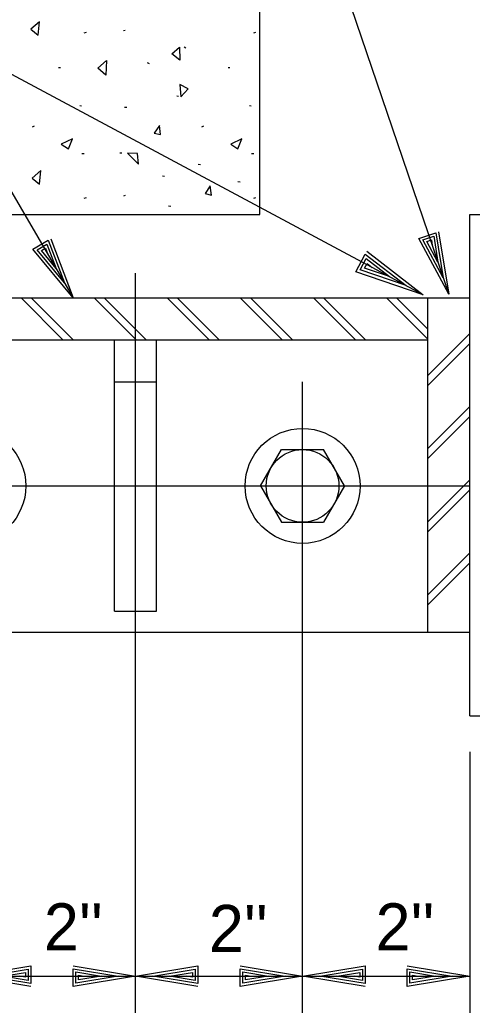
# Model space of a CAD drawing. Extents: x 22369.6 to 22389.4, y 22369.6 to 22386.
# Drawn here: x 22372.355 to 22372.806, y 22372.947 to 22373.93 of the extents above; entities that cross this region are included whole.
import ezdxf

# ---------------------------------------------------------------- set-up
doc = ezdxf.new("R2010")
doc.units = 0
for name, color, linetype in [('Level 1', 7, 'Continuous'), ('Level 10', 7, 'Continuous'), ('Level 2', 7, 'Continuous'), ('Level 4', 7, 'Continuous'), ('Level 50', 7, 'Continuous'), ('Level 7', 7, 'Continuous')]:
    doc.layers.add(name, color=color, linetype=linetype)

msp = doc.modelspace()

# ---------------------------------------------------------------- linework, layer by layer
at = {"layer": 'Level 1'}
for p, q in [((22372.4704, 22372.92825), (22372.4704, 22373.67725)), ((22372.39808, 22373.61084), (22372.35621, 22373.65272)), ((22372.40814, 22373.61084), (22372.36627, 22373.65272)), ((22372.471, 22373.61084), (22372.42912, 22373.65272)), ((22372.48105, 22373.61084), (22372.43918, 22373.65272)), ((22372.5439, 22373.61084), (22372.50203, 22373.65272)), ((22372.55397, 22373.61084), (22372.51209, 22373.65272)), ((22372.61682, 22373.61084), (22372.57495, 22373.65272)), ((22372.62687, 22373.61084), (22372.585, 22373.65272)), ((22372.68973, 22373.61084), (22372.64785, 22373.65272)), ((22372.69978, 22373.61084), (22372.6579, 22373.65272)), ((22372.76165, 22373.61182), (22372.72076, 22373.65272)), ((22372.76207, 22373.62147), (22372.73082, 22373.65272)), ((22372.76186, 22373.57539), (22372.80374, 22373.61727)), ((22372.76186, 22373.56534), (22372.80374, 22373.60722)), ((22372.63707, 22372.92308), (22372.63707, 22373.56918)), ((22372.76186, 22373.50249), (22372.80374, 22373.54436)), ((22372.76186, 22373.49244), (22372.80374, 22373.53431)), ((22372.59518, 22373.4653), (22372.61618, 22373.50168)), ((22372.61618, 22373.50168), (22372.65797, 22373.50168)), ((22372.67897, 22373.4653), (22372.65797, 22373.50168)), ((22372.76186, 22373.42958), (22372.80374, 22373.47146)), ((22372.13707, 22373.46522), (22372.80374, 22373.46522)), ((22372.59518, 22373.4653), (22372.61618, 22373.42895)), ((22372.67897, 22373.4653), (22372.65797, 22373.42895)), ((22372.76186, 22373.41952), (22372.80374, 22373.46139)), ((22372.61618, 22373.42895), (22372.65797, 22373.42895)), ((22372.76186, 22373.35666), (22372.80374, 22373.39854)), ((22372.76186, 22373.34661), (22372.80374, 22373.38849)), ((22372.80374, 22373.2), (22372.80374, 22372.76258)), ((22372.30374, 22372.9763), (22372.4704, 22372.9763)), ((22372.4704, 22372.9763), (22372.63707, 22372.9763)), ((22372.63707, 22372.9763), (22372.80374, 22372.9763))]:
    msp.add_line(p, q, dxfattribs=at)
for centre, radius in [((22372.30374, 22373.46522), 0.05729), ((22372.63707, 22373.46522), 0.05729), ((22372.63707, 22373.46522), 0.03627)]:
    msp.add_circle(centre, radius, dxfattribs=at)
at = {"layer": 'Level 10'}
for p, q in [((22372.75741, 22373.6559), (22371.83286, 22374.15046)), ((22372.74023, 22373.66509), (22372.74023, 22373.66509)), ((22372.75741, 22373.6559), (22372.75741, 22373.6559))]:
    msp.add_line(p, q, dxfattribs=at)
msp.add_lwpolyline([(22372.70106, 22373.69923), (22372.75741, 22373.6559), (22372.6901, 22373.67873), (22372.69948, 22373.69626), (22372.74023, 22373.66509), (22372.69451, 22373.68062), (22372.70053, 22373.69186), (22372.72369, 22373.67395), (22372.69893, 22373.68251), (22372.7014, 22373.68713), (22372.7065, 22373.68314)], dxfattribs=at)
at = {"layer": 'Level 2'}
for p, q in [((22372.39962, 22373.6677), (22372.39962, 22373.6677)), ((22372.7774, 22373.67273), (22372.7774, 22373.67273)), ((22372.78299, 22373.65632), (22372.78299, 22373.65632)), ((22372.40835, 22373.65272), (22372.40835, 22373.65272)), ((22372.45307, 22372.9763), (22372.45307, 22372.9763)), ((22372.4704, 22372.9763), (22372.4704, 22372.9763)), ((22372.4704, 22372.9763), (22372.4704, 22372.9763)), ((22372.48774, 22372.9763), (22372.48774, 22372.9763)), ((22372.61974, 22372.9763), (22372.61974, 22372.9763)), ((22372.63707, 22372.9763), (22372.63707, 22372.9763)), ((22372.63707, 22372.9763), (22372.63707, 22372.9763)), ((22372.6544, 22372.9763), (22372.6544, 22372.9763)), ((22372.7864, 22372.9763), (22372.7864, 22372.9763)), ((22372.80374, 22372.9763), (22372.80374, 22372.9763))]:
    msp.add_line(p, q, dxfattribs=at)
for points in [[(22371.81397, 22374.53041), (22371.89695, 22374.53041), (22372.40835, 22373.65272)], [(22372.68011, 22373.95839), (22372.78299, 22373.65632)], [(22372.77268, 22373.71865), (22372.78299, 22373.65632), (22372.75311, 22373.712), (22372.76983, 22373.71769), (22372.7774, 22373.67273), (22372.75712, 22373.71055), (22372.76785, 22373.7142), (22372.77203, 22373.68851), (22372.76114, 22373.70909), (22372.76556, 22373.7106), (22372.76644, 22373.70491)], [(22372.3859, 22373.71178), (22372.40835, 22373.65272), (22372.36804, 22373.70137), (22372.38331, 22373.71027), (22372.39962, 22373.6677), (22372.37227, 22373.70075), (22372.38206, 22373.70646), (22372.39124, 22373.68209), (22372.37649, 22373.70012), (22372.38052, 22373.70247), (22372.38251, 22373.69707)], [(22372.36607, 22372.96597), (22372.30374, 22372.9763), (22372.36607, 22372.98663), (22372.36607, 22372.96897), (22372.32107, 22372.9763), (22372.3634, 22372.9833), (22372.3634, 22372.97197), (22372.33774, 22372.9763), (22372.36074, 22372.97997), (22372.36074, 22372.9753), (22372.35507, 22372.9763)], [(22372.40807, 22372.98663), (22372.4704, 22372.9763), (22372.40807, 22372.96597), (22372.40807, 22372.98363), (22372.45307, 22372.9763), (22372.41074, 22372.9693), (22372.41074, 22372.98063), (22372.4364, 22372.9763), (22372.4134, 22372.97263), (22372.4134, 22372.9773), (22372.41907, 22372.9763)], [(22372.53274, 22372.96597), (22372.4704, 22372.9763), (22372.53274, 22372.98663), (22372.53274, 22372.96897), (22372.48774, 22372.9763), (22372.53007, 22372.9833), (22372.53007, 22372.97197), (22372.5044, 22372.9763), (22372.5274, 22372.97997), (22372.5274, 22372.9753), (22372.52174, 22372.9763)], [(22372.57474, 22372.98663), (22372.63707, 22372.9763), (22372.57474, 22372.96597), (22372.57474, 22372.98363), (22372.61974, 22372.9763), (22372.5774, 22372.9693), (22372.5774, 22372.98063), (22372.60307, 22372.9763), (22372.58007, 22372.97263), (22372.58007, 22372.9773), (22372.58574, 22372.9763)], [(22372.6994, 22372.96597), (22372.63707, 22372.9763), (22372.6994, 22372.98663), (22372.6994, 22372.96897), (22372.6544, 22372.9763), (22372.69674, 22372.9833), (22372.69674, 22372.97197), (22372.67107, 22372.9763), (22372.69407, 22372.97997), (22372.69407, 22372.9753), (22372.6884, 22372.9763)], [(22372.7414, 22372.98663), (22372.80374, 22372.9763), (22372.7414, 22372.96597), (22372.7414, 22372.98363), (22372.7864, 22372.9763), (22372.74407, 22372.9693), (22372.74407, 22372.98063), (22372.76974, 22372.9763), (22372.74674, 22372.97263), (22372.74674, 22372.9773), (22372.7524, 22372.9763)]]:
    msp.add_lwpolyline(points, dxfattribs=at)
at = {"layer": 'Level 50'}
for p, q in [((22372.42107, 22373.91727), (22372.41881, 22373.91664)), ((22372.42107, 22373.91727), (22372.41881, 22373.91664)), ((22372.4601, 22373.91953), (22372.45847, 22373.9189)), ((22372.4601, 22373.91953), (22372.45847, 22373.9189)), ((22372.4601, 22373.91953), (22372.45847, 22373.9189)), ((22372.59025, 22373.91727), (22372.58799, 22373.91664)), ((22372.59025, 22373.91727), (22372.58799, 22373.91664)), ((22372.59025, 22373.91727), (22372.58799, 22373.91664)), ((22372.52074, 22373.90177), (22372.51885, 22373.9029)), ((22372.52074, 22373.90177), (22372.51885, 22373.9029)), ((22372.52074, 22373.90177), (22372.51885, 22373.9029)), ((22372.39545, 22373.88218), (22372.3936, 22373.88201)), ((22372.39545, 22373.88218), (22372.3936, 22373.88201)), ((22372.39545, 22373.88218), (22372.3936, 22373.88201)), ((22372.48426, 22373.8862), (22372.48247, 22373.88703)), ((22372.48426, 22373.8862), (22372.48247, 22373.88703)), ((22372.48426, 22373.8862), (22372.48247, 22373.88703)), ((22372.56462, 22373.88218), (22372.56278, 22373.88201)), ((22372.56462, 22373.88218), (22372.56278, 22373.88201)), ((22372.56462, 22373.88218), (22372.56278, 22373.88201)), ((22372.5132, 22373.85366), (22372.51152, 22373.85379)), ((22372.5132, 22373.85366), (22372.51152, 22373.85379)), ((22372.5132, 22373.85366), (22372.51152, 22373.85379)), ((22372.41659, 22373.84386), (22372.41491, 22373.84415)), ((22372.41659, 22373.84386), (22372.41491, 22373.84415)), ((22372.41659, 22373.84386), (22372.41491, 22373.84415)), ((22372.46165, 22373.84244), (22372.45939, 22373.84244)), ((22372.46165, 22373.84244), (22372.45939, 22373.84244)), ((22372.46165, 22373.84244), (22372.45939, 22373.84244)), ((22372.58577, 22373.84386), (22372.58409, 22373.84415)), ((22372.58577, 22373.84386), (22372.58409, 22373.84415)), ((22372.58577, 22373.84386), (22372.58409, 22373.84415)), ((22372.36919, 22373.82413), (22372.36718, 22373.82313)), ((22372.36919, 22373.82413), (22372.36718, 22373.82313)), ((22372.36919, 22373.82413), (22372.36718, 22373.82313)), ((22372.53836, 22373.82413), (22372.53635, 22373.82313)), ((22372.53836, 22373.82413), (22372.53635, 22373.82313)), ((22372.53836, 22373.82413), (22372.53635, 22373.82313)), ((22372.41927, 22373.79633), (22372.41701, 22373.79633)), ((22372.41927, 22373.79633), (22372.41701, 22373.79633)), ((22372.41927, 22373.79633), (22372.41701, 22373.79633)), ((22372.45679, 22373.79713), (22372.45465, 22373.79713)), ((22372.45679, 22373.79713), (22372.45465, 22373.79713)), ((22372.45679, 22373.79713), (22372.45465, 22373.79713)), ((22372.58845, 22373.79633), (22372.58619, 22373.79633)), ((22372.58845, 22373.79633), (22372.58619, 22373.79633)), ((22372.58845, 22373.79633), (22372.58619, 22373.79633)), ((22372.53519, 22373.78543), (22372.53301, 22373.78581)), ((22372.49943, 22373.77372), (22372.49725, 22373.7741)), ((22372.49943, 22373.77372), (22372.49725, 22373.7741)), ((22372.49943, 22373.77372), (22372.49725, 22373.7741)), ((22372.57465, 22373.76802), (22372.57248, 22373.7684)), ((22372.4601, 22373.75475), (22372.45847, 22373.75412)), ((22372.4601, 22373.75475), (22372.45847, 22373.75412)), ((22372.4601, 22373.75475), (22372.45847, 22373.75412)), ((22372.42107, 22373.75249), (22372.41881, 22373.75186)), ((22372.42107, 22373.75249), (22372.41881, 22373.75186)), ((22372.42107, 22373.75249), (22372.41881, 22373.75186)), ((22372.5055, 22373.74398), (22372.50332, 22373.74436)), ((22372.59025, 22373.75249), (22372.58799, 22373.75186)), ((22372.59025, 22373.75249), (22372.58799, 22373.75186)), ((22372.59025, 22373.75249), (22372.58799, 22373.75186))]:
    msp.add_line(p, q, dxfattribs=at)
for points in [[(22372.37464, 22373.92808), (22372.36606, 22373.92058), (22372.37319, 22373.91459)], [(22372.51479, 22373.88993), (22372.50675, 22373.896), (22372.51446, 22373.90282)], [(22372.51479, 22373.88993), (22372.50675, 22373.896), (22372.51446, 22373.90282)], [(22372.51479, 22373.88993), (22372.50675, 22373.896), (22372.51446, 22373.90282)], [(22372.44072, 22373.87481), (22372.43297, 22373.88197), (22372.44155, 22373.88963)], [(22372.44072, 22373.87481), (22372.43297, 22373.88197), (22372.44155, 22373.88963)], [(22372.44072, 22373.87481), (22372.43297, 22373.88197), (22372.44155, 22373.88963)], [(22372.51562, 22373.85307), (22372.52279, 22373.86111), (22372.51479, 22373.86538)], [(22372.51562, 22373.85307), (22372.52279, 22373.86111), (22372.51479, 22373.86538)], [(22372.51562, 22373.85307), (22372.52279, 22373.86111), (22372.51479, 22373.86538)], [(22372.49549, 22373.81563), (22372.49431, 22373.82481), (22372.48916, 22373.81714)], [(22372.49549, 22373.81563), (22372.49431, 22373.82481), (22372.48916, 22373.81714)], [(22372.49549, 22373.81563), (22372.49431, 22373.82481), (22372.48916, 22373.81714)], [(22372.40345, 22373.80123), (22372.40743, 22373.81149), (22372.39632, 22373.80609)], [(22372.40345, 22373.80123), (22372.40743, 22373.81149), (22372.39632, 22373.80609)], [(22372.40345, 22373.80123), (22372.40743, 22373.81149), (22372.39632, 22373.80609)], [(22372.57262, 22373.80123), (22372.57659, 22373.81149), (22372.5655, 22373.80609)], [(22372.57262, 22373.80123), (22372.57659, 22373.81149), (22372.5655, 22373.80609)], [(22372.57262, 22373.80123), (22372.57659, 22373.81149), (22372.5655, 22373.80609)], [(22372.4725, 22373.79658), (22372.46245, 22373.79713), (22372.47333, 22373.78599)], [(22372.4725, 22373.79658), (22372.46245, 22373.79713), (22372.47333, 22373.78599)], [(22372.4725, 22373.79658), (22372.46245, 22373.79713), (22372.47333, 22373.78599)], [(22372.37598, 22373.77975), (22372.36739, 22373.77226), (22372.37451, 22373.76627)], [(22372.37598, 22373.77975), (22372.36739, 22373.77226), (22372.37451, 22373.76627)], [(22372.37598, 22373.77975), (22372.36739, 22373.77226), (22372.37451, 22373.76627)], [(22372.54609, 22373.75521), (22372.54491, 22373.76438), (22372.53977, 22373.75672)]]:
    msp.add_lwpolyline(points, close=True, dxfattribs=at)
at = {"layer": 'Level 7'}
for p, q in [((22372.59435, 22373.73605), (22372.59435, 22374.79496)), ((22371.24699, 22373.73605), (22372.59435, 22373.73605)), ((22372.80374, 22373.23605), (22372.80374, 22373.73605)), ((22372.80374, 22373.73605), (22372.8454, 22373.73605)), ((22372.13707, 22373.65272), (22372.80374, 22373.65272)), ((22372.76207, 22373.31938), (22372.76207, 22373.65272)), ((22372.13707, 22373.61084), (22372.76207, 22373.61084)), ((22372.44957, 22373.34022), (22372.44957, 22373.61084)), ((22372.49124, 22373.34022), (22372.49124, 22373.61084)), ((22372.44957, 22373.56918), (22372.49124, 22373.56918)), ((22372.44957, 22373.34022), (22372.49124, 22373.34022)), ((22372.13707, 22373.31938), (22372.80374, 22373.31938)), ((22372.80374, 22373.23605), (22372.8454, 22373.23605))]:
    msp.add_line(p, q, dxfattribs=at)

# ---------------------------------------------------------------- texts
at = {"layer": 'Level 4'}
for p in [(22372.37908, 22373.00212), (22372.54361, 22373.0005), (22372.70987, 22373.00211)]:
    msp.add_text("2''", height=0.046875, dxfattribs=at).set_placement(p)

doc.saveas('drawing.dxf')
